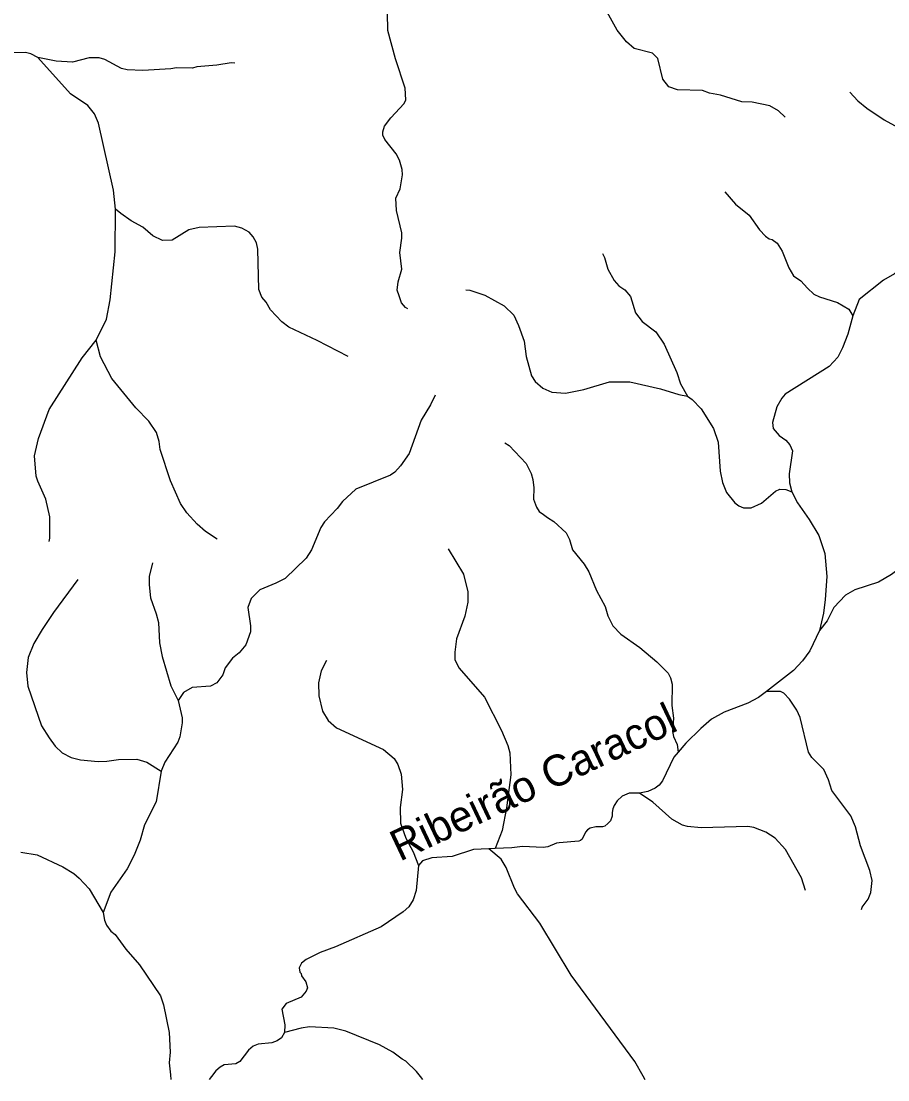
# Model space of a CAD drawing. Extents: x 500 to 555.2, y 9115.7 to 9171.
# Drawn here: x 539.23 to 544.8, y 9115.68 to 9122.5 of the extents above; entities that cross this region are included whole.
import ezdxf
from ezdxf.enums import TextEntityAlignment as Align

# ---------------------------------------------------------------- set-up
doc = ezdxf.new("R2010")
doc.units = 0
doc.header["$LTSCALE"] = 0.064
doc.layers.add('61', color=7, linetype='Continuous')
doc.layers.add('7', color=7, linetype='Continuous', lineweight=25)

msp = doc.modelspace()

# ---------------------------------------------------------------- linework, layer by layer
at = {"layer": '7'}
for points in [[(544.1442, 9121.879), (544.1021, 9121.9201), (544.0457, 9121.9513), (543.9321, 9121.9744), (543.8665, 9121.9778), (543.728, 9122.019), (543.658, 9122.0328), (543.6133, 9122.0495), (543.4509, 9122.0547), (543.396, 9122.0738), (543.3561, 9122.122), (543.3245, 9122.2563), (543.2911, 9122.2909), (543.1734, 9122.3207), (543.1233, 9122.3643), (543.0626, 9122.4396), (542.9883, 9122.5746), (542.9253, 9122.6744), (542.8964, 9122.7393), (542.8604, 9122.9092), (542.8339, 9122.9781)], [(541.7158, 9120.6436), (541.7004, 9120.6534), (541.6759, 9120.6823), (541.6592, 9120.7273), (541.6483, 9120.7637), (541.6534, 9120.8168), (541.6778, 9120.8988), (541.6647, 9121.0071), (541.6778, 9121.0989), (541.6779, 9121.1342), (541.6421, 9121.2767), (541.6384, 9121.3573), (541.6662, 9121.4166), (541.6826, 9121.5063), (541.6795, 9121.5405), (541.6627, 9121.6008), (541.6417, 9121.6429), (541.5688, 9121.7336), (541.5548, 9121.7624), (541.5549, 9121.7839), (541.5651, 9121.8204), (541.6066, 9121.8736), (541.692, 9121.9659), (541.7022, 9121.9897), (541.6993, 9122.064), (541.6366, 9122.2537), (541.5876, 9122.4369), (541.5844, 9122.5496)], [(539.3346, 9122.2618), (539.2888, 9122.2861), (539.2551, 9122.2941), (539.0773, 9122.2909), (539.0036, 9122.3038), (538.9478, 9122.3405), (538.8565, 9122.4252), (538.8015, 9122.4481)], [(540.6034, 9122.2253), (540.5782, 9122.228), (540.4864, 9122.2123), (540.358, 9122.2022), (540.331, 9122.1941), (540.2268, 9122.197), (540.1912, 9122.1892), (540.0109, 9122.1793), (539.9086, 9122.1826), (539.8733, 9122.192), (539.7651, 9122.2506), (539.7302, 9122.2613), (539.6652, 9122.2596), (539.5587, 9122.2335), (539.4526, 9122.2399), (539.3346, 9122.2618)], [(539.8342, 9121.2863), (539.8225, 9121.4074), (539.726, 9121.8391), (539.6996, 9121.8988), (539.6564, 9121.9534), (539.5459, 9122.0296), (539.3346, 9122.2618)], [(544.5605, 9122.0401), (544.6123, 9121.9825), (544.6693, 9121.9353), (544.7821, 9121.8601), (544.8488, 9121.8244), (544.9398, 9121.7924), (544.9791, 9121.7857), (545.0551, 9121.756), (545.1393, 9121.7033), (545.181, 9121.6695), (545.2805, 9121.6091), (545.3349, 9121.5616), (545.3617, 9121.5262), (545.3814, 9121.476), (545.3839, 9121.4412)], [(543.7561, 9121.3973), (543.8257, 9121.319), (543.9131, 9121.2463), (543.98, 9121.1519), (544.0171, 9121.1114), (544.0416, 9121.0951), (544.0611, 9121.09), (544.092, 9121.0673), (544.1261, 9121.0142), (544.1674, 9120.9078), (544.198, 9120.8567), (544.2457, 9120.8251), (544.2876, 9120.7768), (544.3296, 9120.7385), (544.3644, 9120.7205), (544.481, 9120.6848), (544.5546, 9120.6423), (544.5794, 9120.5987)], [(545.3839, 9121.4412), (545.3586, 9121.374), (545.2602, 9121.2247), (545.1984, 9121.1709), (545.1018, 9121.1199), (545.0769, 9121.0986), (545.0064, 9121.0087), (544.9014, 9120.9069), (544.8485, 9120.8688), (544.7765, 9120.8282), (544.6209, 9120.7033), (544.5794, 9120.5987)], [(539.7093, 9120.4411), (539.7755, 9120.5781), (539.7993, 9120.7023), (539.8324, 9121.0116), (539.8348, 9121.2804), (539.8342, 9121.2863)], [(541.3323, 9120.3362), (541.1332, 9120.4405), (540.9501, 9120.5266), (540.9052, 9120.5602), (540.8323, 9120.638), (540.8039, 9120.6868), (540.7767, 9120.7188), (540.7563, 9120.7691), (540.7507, 9121.0283), (540.7414, 9121.0681), (540.7215, 9121.1082), (540.6951, 9121.1377), (540.6466, 9121.1637), (540.6012, 9121.1752), (540.3727, 9121.1671), (540.3065, 9121.1516), (540.1992, 9121.0856), (540.1364, 9121.0837), (540.0737, 9121.1132), (540.0096, 9121.1688), (539.9354, 9121.2106), (539.8698, 9121.2572), (539.8342, 9121.2863)], [(542.9696, 9120.9998), (542.982, 9120.9755), (543.0032, 9120.8983), (543.0441, 9120.8255), (543.0741, 9120.7929), (543.1114, 9120.767), (543.1488, 9120.7225), (543.1817, 9120.6172), (543.2242, 9120.5624), (543.3118, 9120.4958), (543.3655, 9120.416), (543.4475, 9120.2338), (543.4707, 9120.1602), (543.5167, 9120.0815)], [(542.0896, 9120.766), (542.1155, 9120.764), (542.2105, 9120.731), (542.3355, 9120.6636), (542.3973, 9120.6035), (542.4276, 9120.5368), (542.4636, 9120.435), (542.4784, 9120.3367), (542.5114, 9120.2121), (542.5354, 9120.1751), (542.5847, 9120.132), (542.6433, 9120.1062), (542.7314, 9120.1011), (542.8479, 9120.1241), (543.0147, 9120.1732), (543.1442, 9120.1733), (543.3427, 9120.1289), (543.4609, 9120.0912), (543.5167, 9120.0815)], [(544.5794, 9120.5987), (544.548, 9120.481), (544.5135, 9120.3924), (544.4823, 9120.3334), (544.4276, 9120.2715), (544.1443, 9120.0937), (544.1231, 9120.0694), (544.0913, 9120.0137), (544.0629, 9119.9125)], [(539.4072, 9119.1449), (539.4128, 9119.1672), (539.4109, 9119.3038), (539.3863, 9119.4187), (539.3338, 9119.534), (539.3239, 9119.5669), (539.3142, 9119.697), (539.3388, 9119.8091), (539.4071, 9119.9947), (539.621, 9120.329), (539.7093, 9120.4411)], [(540.4886, 9119.1602), (540.4127, 9119.2107), (540.3605, 9119.258), (540.2942, 9119.3296), (540.2538, 9119.3902), (540.1895, 9119.5371), (540.1211, 9119.7375), (540.1162, 9119.7894), (540.0982, 9119.8484), (540.0498, 9119.9195), (539.9661, 9120.0064), (539.8099, 9120.1957), (539.7388, 9120.3345), (539.7093, 9120.4411)], [(541.8915, 9120.0871), (541.8612, 9120.0251), (541.8019, 9119.926), (541.724, 9119.7112), (541.6688, 9119.633), (541.6318, 9119.5926), (541.6043, 9119.5717), (541.381, 9119.4826), (541.296, 9119.4026), (541.2616, 9119.3585), (541.1792, 9119.271), (541.1549, 9119.2348), (541.0956, 9119.0912), (541.0617, 9119.0372), (540.9273, 9118.9078), (540.8663, 9118.876), (540.764, 9118.8349), (540.7084, 9118.7773), (540.6872, 9118.7193), (540.7035, 9118.6024), (540.7035, 9118.563), (540.674, 9118.4807), (540.6301, 9118.4284), (540.5883, 9118.3931), (540.5409, 9118.3322), (540.5248, 9118.2875), (540.4869, 9118.2346), (540.4453, 9118.2146), (540.3276, 9118.2061), (540.2712, 9118.1729), (540.2383, 9118.122)], [(543.5167, 9120.0815), (543.5456, 9120.0607), (543.6039, 9120.0003), (543.6833, 9119.8723), (543.7134, 9119.7855), (543.7259, 9119.5994), (543.7401, 9119.5246), (543.7662, 9119.4608), (543.8195, 9119.3954), (543.8463, 9119.3761), (543.8768, 9119.3633), (543.9253, 9119.3627), (543.9922, 9119.3925), (544.083, 9119.4686), (544.1095, 9119.4815), (544.149, 9119.4796), (544.1878, 9119.4646)], [(544.0629, 9119.9125), (544.0674, 9119.8726), (544.1059, 9119.8282), (544.1486, 9119.7987), (544.1746, 9119.7674), (544.1921, 9119.7303), (544.1694, 9119.5809), (544.1716, 9119.5229), (544.1878, 9119.4646)], [(542.3407, 9119.7801), (542.3687, 9119.764), (542.478, 9119.6471), (542.5089, 9119.5839), (542.5206, 9119.5443), (542.5275, 9119.4912), (542.5244, 9119.4182), (542.5441, 9119.3657), (542.5613, 9119.3378), (542.5894, 9119.319), (542.6147, 9119.2994), (542.6549, 9119.2746), (542.734, 9119.2005), (542.7572, 9119.159), (542.7755, 9119.0924), (542.8506, 9118.9987), (542.8817, 9118.9495), (542.9291, 9118.8288), (542.9851, 9118.7265), (543.0028, 9118.6675), (543.0363, 9118.6013), (543.0869, 9118.5479), (543.2088, 9118.4632), (543.318, 9118.3705), (543.3908, 9118.2971), (543.4066, 9118.2671), (543.4165, 9118.2272), (543.4149, 9118.0887), (543.4248, 9118.0066), (543.4182, 9117.9227), (543.4262, 9117.8905), (543.4493, 9117.8373), (543.4551, 9117.7897)], [(544.1878, 9119.4646), (544.2242, 9119.394), (544.2994, 9119.2869), (544.361, 9119.1831), (544.4007, 9119.0676), (544.4121, 9118.9207), (544.4022, 9118.771), (544.3907, 9118.6832), (544.3659, 9118.573)], [(541.975, 9119.0984), (542.0733, 9118.9359), (542.101, 9118.8216), (542.1025, 9118.7549), (542.083, 9118.6647), (542.0287, 9118.5186), (542.0174, 9118.4318), (542.0189, 9118.3826), (542.0461, 9118.3307), (542.2084, 9118.1428), (542.3194, 9117.9287), (542.3599, 9117.8315), (542.3733, 9117.7849), (542.3786, 9117.6432), (542.3507, 9117.4297), (542.3228, 9117.2844), (542.2787, 9117.1682), (542.2364, 9117.1662)], [(540.0732, 9119.009), (540.0508, 9118.9206), (540.0508, 9118.8665), (540.0604, 9118.7828), (540.097, 9118.6789), (540.1111, 9118.6228), (540.1176, 9118.4923), (540.1344, 9118.4044), (540.1896, 9118.2161), (540.2383, 9118.122)], [(544.9058, 9118.99), (544.8283, 9118.9328), (544.7441, 9118.8843), (544.5937, 9118.8332), (544.5324, 9118.7995), (544.4567, 9118.7213), (544.4149, 9118.634), (544.3659, 9118.573)], [(539.5919, 9118.9003), (539.4359, 9118.6876), (539.3621, 9118.5778), (539.3094, 9118.4875), (539.2715, 9118.3984), (539.2617, 9118.3013), (539.2708, 9118.2144), (539.3592, 9117.9586), (539.4066, 9117.8801), (539.4457, 9117.8281), (539.4908, 9117.7854), (539.5485, 9117.7533), (539.6087, 9117.7387), (539.7228, 9117.7292), (539.7794, 9117.7313), (539.8548, 9117.7424), (539.971, 9117.7438), (540.0359, 9117.7241), (540.1287, 9117.6672)], [(544.3659, 9118.573), (544.3038, 9118.4412), (544.2559, 9118.3765), (544.1984, 9118.3143), (544.0248, 9118.1802)], [(541.1922, 9118.3797), (541.1578, 9118.3126), (541.1399, 9118.235), (541.1432, 9118.1511), (541.1666, 9118.0527), (541.2021, 9117.992), (541.2558, 9117.9446), (541.5584, 9117.8055), (541.6277, 9117.7482), (541.6524, 9117.7089), (541.6728, 9117.6472), (541.6811, 9117.5487), (541.6664, 9117.4319), (541.6681, 9117.3317), (541.7027, 9117.2348), (541.7495, 9117.1462), (541.7846, 9117.0591)], [(540.2383, 9118.122), (540.2634, 9118.0108), (540.2637, 9117.9771), (540.2492, 9117.8873), (540.2356, 9117.8532), (540.1515, 9117.7237), (540.1287, 9117.6672)], [(544.0248, 9118.1802), (543.973, 9118.1402), (543.9031, 9118.1046), (543.7522, 9118.047), (543.6703, 9118.0007), (543.6013, 9117.9417), (543.5046, 9117.8468), (543.4551, 9117.7897)], [(544.6365, 9116.7746), (544.6408, 9116.7898), (544.6785, 9116.8417), (544.6962, 9116.8839), (544.7041, 9116.9615), (544.6893, 9117.0271), (544.6288, 9117.1847), (544.596, 9117.3088), (544.5677, 9117.3782), (544.4444, 9117.5421), (544.4236, 9117.6111), (544.3924, 9117.6766), (544.3165, 9117.7543), (544.2945, 9117.7891), (544.2412, 9118.0111), (544.2189, 9118.0599), (544.1726, 9118.1294), (544.1358, 9118.1695), (544.1134, 9118.1784), (544.0248, 9118.1802)], [(543.4551, 9117.7897), (543.4268, 9117.7569), (543.3554, 9117.604), (543.3343, 9117.5768), (543.3074, 9117.5559), (543.2612, 9117.5358), (543.2078, 9117.5243)], [(540.1287, 9117.6672), (540.0961, 9117.4686), (540.0218, 9117.3206), (539.9937, 9117.2222), (539.9538, 9117.1256), (539.9095, 9117.0371), (539.804, 9116.888), (539.7546, 9116.7555)], [(543.2078, 9117.5243), (543.1393, 9117.5239), (543.0955, 9117.5049), (543.0634, 9117.4743), (543.0435, 9117.4458), (543.0348, 9117.4234), (543.0314, 9117.3994), (543.0306, 9117.3755), (543.0195, 9117.3456), (543.0027, 9117.3285), (542.9843, 9117.312), (542.9696, 9117.307), (542.9267, 9117.3076), (542.8896, 9117.2989), (542.8724, 9117.289), (542.8602, 9117.2725), (542.8371, 9117.2291), (542.8269, 9117.219), (542.8158, 9117.2145), (542.6898, 9117.2042), (542.6727, 9117.2018), (542.6171, 9117.178), (542.5877, 9117.175), (542.4536, 9117.1813), (542.3842, 9117.1731), (542.2787, 9117.1682)], [(544.2746, 9116.8973), (544.2489, 9116.9797), (544.1461, 9117.1621), (544.0801, 9117.2345), (544.0191, 9117.2737), (543.9436, 9117.3025), (543.9032, 9117.3109), (543.6037, 9117.3011), (543.5161, 9117.3089), (543.4832, 9117.3183), (543.4144, 9117.3573), (543.2935, 9117.4667), (543.2078, 9117.5243)], [(542.2364, 9117.1662), (542.1394, 9117.1616), (542.0016, 9117.116), (541.8704, 9117.1075), (541.8095, 9117.0898), (541.7846, 9117.0591)], [(543.2433, 9115.6784), (543.2301, 9115.702), (543.177, 9115.7969), (542.7679, 9116.3533), (542.5659, 9116.6873), (542.4222, 9116.8768), (542.4022, 9116.9138), (542.3486, 9117.0468), (542.3161, 9117.1003), (542.2364, 9117.1662)], [(539.2256, 9117.1452), (539.3305, 9117.1272), (539.496, 9117.0509), (539.5654, 9117.0068), (539.6006, 9116.9768), (539.6645, 9116.9076), (539.7546, 9116.7555)], [(541.7846, 9117.0591), (541.7698, 9116.8974), (541.75, 9116.8369), (541.7228, 9116.7936), (541.6855, 9116.761), (541.5452, 9116.663), (541.2503, 9116.5353), (541.1507, 9116.4986), (541.0618, 9116.4544), (541.0313, 9116.4294), (541.017, 9116.4005), (541.0215, 9116.3725), (541.0298, 9116.3622), (541.0309, 9116.3489), (541.0605, 9116.3098), (541.0691, 9116.2709), (541.0609, 9116.2497), (541.0291, 9116.2101), (540.9332, 9116.1707), (540.9054, 9116.1342), (540.9245, 9116.0322), (540.9231, 9115.9829)], [(539.7546, 9116.7555), (539.7634, 9116.7063), (539.7759, 9116.6749), (539.8051, 9116.6363), (539.8333, 9116.614), (539.9012, 9116.5209), (539.9897, 9116.4195), (540.1246, 9116.2195), (540.1427, 9116.1605), (540.1802, 9115.9839), (540.1866, 9115.8555), (540.1803, 9115.7889), (540.1885, 9115.71), (540.1915, 9115.6813)], [(541.8125, 9115.6798), (541.7973, 9115.6994), (541.772, 9115.732), (541.7035, 9115.799), (541.6791, 9115.8106), (541.619, 9115.8567), (541.5345, 9115.9038), (541.3162, 9115.9912), (541.2398, 9116.0101), (541.0824, 9116.0199), (541.0293, 9116.0117), (540.9231, 9115.9829)], [(540.9231, 9115.9829), (540.9027, 9115.9495), (540.8742, 9115.9303), (540.8411, 9115.9157), (540.7517, 9115.9084), (540.7197, 9115.8944), (540.6904, 9115.869), (540.6344, 9115.7954), (540.6085, 9115.7819), (540.5348, 9115.7743), (540.5072, 9115.7605), (540.4796, 9115.7363), (540.4526, 9115.7002), (540.4373, 9115.681)]]:
    msp.add_lwpolyline(points, dxfattribs=at)

# ---------------------------------------------------------------- texts
at = {"layer": '61'}
msp.add_text('Ribeirão Caracol', height=0.2, rotation=25.263, dxfattribs=at).set_placement((542.5644, 9117.5073), align=Align.CENTER)

doc.saveas('drawing.dxf')
